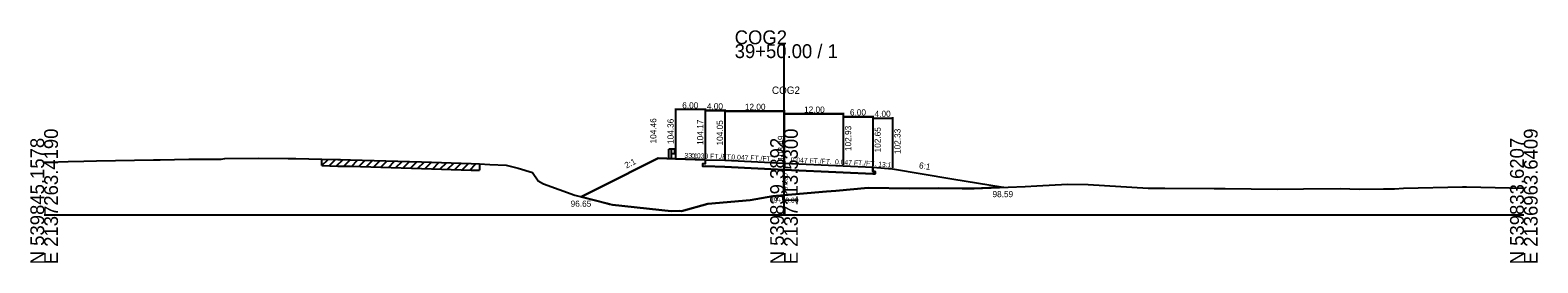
# Model space of a CAD drawing. Extents: x -13397 to 2303, y -10 to 39059.
# Drawn here: x 997.2 to 1302.8, y 18990.3 to 19037.4 of the extents above; entities that cross this region are included whole.
import ezdxf

# ---------------------------------------------------------------- set-up
doc = ezdxf.new("R2010")
doc.units = 0
for name, color, linetype in [('Level 1', 7, 'Continuous'), ('Level 5', 7, 'Continuous'), ('Level 53', 7, 'Continuous'), ('Level 54', 7, 'Continuous'), ('Level 55', 7, 'Continuous'), ('Level 7', 7, 'Continuous'), ('RD_GPK_XS_Cell', 7, 'Continuous'), ('RD_XS_EwShp', 7, 'Continuous'), ('RD_XS_ExGround', 7, 'Continuous'), ('RD_XS_ExPaveRet', 7, 'Continuous'), ('RD_XS_Pave', 7, 'Continuous'), ('RD_XS_TX_Baseline', 7, 'Continuous'), ('RD_XS_TX_Elev_EX', 7, 'Continuous'), ('RD_XS_TX_Elev_PR', 7, 'Continuous'), ('RD_XS_TX_Station', 7, 'Continuous')]:
    doc.layers.add(name, color=color, linetype=linetype)

msp = doc.modelspace()

# ---------------------------------------------------------------- linework, layer by layer
at = {"layer": 'Level 1'}
for p, q in [((1126.66, 19011.36), (1126.66, 19013.34)), ((1127.22, 19013.34), (1126.66, 19013.34)), ((1127.22, 19011.36), (1127.22, 19013.34)), ((1127.77, 19013.34), (1127.22, 19013.34)), ((1127.77, 19012.37), (1127.22, 19012.37)), ((1127.77, 19013.34), (1127.77, 19012.37)), ((1127.85, 19013.27), (1127.77, 19013.28)), ((1127.85, 19012.44), (1127.77, 19012.43)), ((1127.84, 19012.93), (1127.84, 19012.78)), ((1127.98, 19013.17), (1127.86, 19013.26)), ((1127.98, 19013.07), (1127.86, 19012.98)), ((1127.98, 19012.64), (1127.86, 19012.73)), ((1127.98, 19012.54), (1127.86, 19012.45))]:
    msp.add_line(p, q, dxfattribs=at)
for centre, radius, start, end in [((1127.91, 19012.93), 0.0651, 135, 180), ((1127.91, 19012.78), 0.0651, 180, 237.0105), ((1127.85, 19013.24), 0.026, 50.9495, 90), ((1127.85, 19012.47), 0.026, 270, 309.0504), ((1127.93, 19013.12), 0.0651, 309.0337, 50.9664), ((1127.93, 19012.59), 0.0651, 309.0337, 50.9664)]:
    msp.add_arc(centre, radius, start, end, dxfattribs=at)
at = {"layer": 'Level 5'}
for p, q in [((1133.5, 19010.36), (1133.5, 19009.86)), ((1134, 19010.34), (1133.5, 19010.36)), ((1134, 19011.17), (1134, 19010.34)), ((1133.5, 19009.86), (1134, 19009.84)), ((1138, 19009.72), (1134, 19009.84)), ((1138, 19009.72), (1134, 19009.84)), ((1138, 19009.72), (1134, 19009.84)), ((1134, 19009.84), (1138, 19009.72)), ((1150, 19009.16), (1138, 19009.72)), ((1150, 19009.16), (1138, 19009.72)), ((1150, 19009.16), (1138, 19009.72)), ((1138, 19009.72), (1150, 19009.16)), ((1138, 19009.72), (1150, 19009.16)), ((1162, 19008.59), (1150, 19009.16)), ((1162, 19008.59), (1150, 19009.16)), ((1150, 19009.16), (1162, 19008.59)), ((1150, 19009.16), (1162, 19008.59)), ((1150, 19009.16), (1162, 19008.59)), ((1168, 19008.31), (1162, 19008.59)), ((1162, 19008.59), (1168, 19008.31)), ((1162, 19008.59), (1168, 19008.31)), ((1162, 19008.59), (1168, 19008.31)), ((1168, 19009.65), (1168, 19008.81)), ((1168, 19008.81), (1168.5, 19008.79)), ((1168.5, 19008.29), (1168, 19008.31)), ((1168.5, 19008.79), (1168.5, 19008.29))]:
    msp.add_line(p, q, dxfattribs=at)
at = {"layer": 'Level 54'}
for p, q in [((1128, 19021.51), (1128, 19011.56)), ((1134, 19021.31), (1128, 19021.31)), ((1134, 19021.51), (1134, 19011.37)), ((1134, 19021.32), (1134, 19011.37)), ((1134, 19021.32), (1134, 19011.37)), ((1134, 19021.32), (1134, 19011.37)), ((1134, 19021.32), (1134, 19011.37)), ((1134, 19021.12), (1138, 19021.12)), ((1134, 19021.12), (1138, 19021.12)), ((1134, 19021.12), (1138, 19021.12)), ((1138, 19021.12), (1134, 19021.12)), ((1138, 19021.32), (1138, 19011.25)), ((1138, 19021.32), (1138, 19011.25)), ((1138, 19021.32), (1138, 19011.25)), ((1138, 19021.32), (1138, 19011.25)), ((1138, 19021.2), (1138, 19011.25)), ((1138, 19021.2), (1138, 19011.25)), ((1138, 19021.2), (1138, 19011.25)), ((1138, 19021.2), (1138, 19011.25)), ((1138, 19021.2), (1138, 19011.25)), ((1138, 19021), (1150, 19021)), ((1138, 19021), (1150, 19021)), ((1138, 19021), (1150, 19021)), ((1150, 19021), (1138, 19021)), ((1150, 19021), (1138, 19021)), ((1150, 19021.2), (1150, 19010.69)), ((1150, 19021.2), (1150, 19010.69)), ((1150, 19021.2), (1150, 19010.69)), ((1150, 19021.2), (1150, 19010.69)), ((1150, 19021.2), (1150, 19010.69)), ((1150, 19020.64), (1150, 19010.69)), ((1150, 19020.64), (1150, 19010.69)), ((1150, 19020.64), (1150, 19010.69)), ((1150, 19020.64), (1150, 19010.69)), ((1150, 19020.64), (1150, 19010.69)), ((1150, 19020.44), (1162, 19020.44)), ((1150, 19020.44), (1162, 19020.44)), ((1162, 19020.44), (1150, 19020.44)), ((1162, 19020.44), (1150, 19020.44)), ((1162, 19020.44), (1150, 19020.44)), ((1162, 19020.64), (1162, 19010.13)), ((1162, 19020.64), (1162, 19010.13)), ((1162, 19020.64), (1162, 19010.13)), ((1162, 19020.64), (1162, 19010.13)), ((1162, 19020.64), (1162, 19010.13)), ((1162, 19020.08), (1162, 19010.13)), ((1162, 19020.08), (1162, 19010.13)), ((1162, 19020.08), (1162, 19010.13)), ((1162, 19020.08), (1162, 19010.13)), ((1162, 19019.88), (1168, 19019.88)), ((1168, 19019.88), (1162, 19019.88)), ((1168, 19019.88), (1162, 19019.88)), ((1168, 19019.88), (1162, 19019.88)), ((1168, 19020.08), (1168, 19009.85)), ((1168, 19020.08), (1168, 19009.85)), ((1168, 19020.08), (1168, 19009.85)), ((1168, 19020.08), (1168, 19009.85)), ((1168, 19019.8), (1168, 19009.85)), ((1168, 19019.6), (1172, 19019.6)), ((1172, 19019.8), (1172, 19009.53))]:
    msp.add_line(p, q, dxfattribs=at)
at = {"layer": 'Level 7'}
for p, q in [((1124.5, 19011.46), (1112.5, 19005.46)), ((1128, 19011.36), (1124.5, 19011.46)), ((1134, 19011.17), (1128, 19011.36)), ((1168, 19009.65), (1172, 19009.33)), ((1172, 19009.33), (1184, 19007.33)), ((1184, 19007.33), (1194.42, 19005.59)), ((1112.5, 19005.46), (1108.87, 19003.65))]:
    msp.add_line(p, q, dxfattribs=at)
at = {"layer": 'RD_GPK_XS_Cell'}
for p, q in [((1150, 19000), (1150, 19034.55)), ((1000, 19000), (1150, 19000)), ((1150, 19000), (1300, 19000))]:
    msp.add_line(p, q, dxfattribs=at)
at = {"layer": 'RD_XS_EwShp'}
msp.add_lwpolyline([(1134, 19011.17), (1134, 19010.34), (1133.5, 19010.36), (1133.5, 19009.86), (1134, 19009.84), (1138, 19009.72), (1150, 19009.16), (1162, 19008.59), (1168, 19008.31), (1168.5, 19008.29), (1168.5, 19008.79), (1168, 19008.81), (1168, 19009.65), (1172, 19009.33), (1184, 19007.33), (1194.42, 19005.59), (1188.54, 19005.38), (1186.09, 19005.34), (1181.31, 19005.43), (1175.54, 19005.35), (1167.06, 19005.47), (1160.52, 19004.86), (1158.63, 19004.76), (1150, 19004), (1147.74, 19003.8), (1143.13, 19003), (1134.58, 19002.23), (1129.24, 19000.76), (1128.85, 19000.85), (1127.1, 19000.79), (1115.25, 19002.05), (1114.65, 19002.17), (1114.15, 19002.31), (1108.87, 19003.65), (1112.5, 19005.46), (1124.5, 19011.46), (1128, 19011.36)], close=True, dxfattribs=at)
at = {"layer": 'RD_XS_ExGround'}
for p, q in [((1000, 19010.65), (1000.87, 19010.69)), ((1000.87, 19010.69), (1004.87, 19010.8)), ((1004.87, 19010.8), (1008.05, 19010.89)), ((1008.05, 19010.89), (1010.6, 19010.94)), ((1010.6, 19010.94), (1022.19, 19011.16)), ((1022.19, 19011.16), (1023.55, 19011.18)), ((1023.55, 19011.18), (1029.32, 19011.3)), ((1029.32, 19011.3), (1033.56, 19011.29)), ((1033.56, 19011.29), (1034.77, 19011.27)), ((1034.77, 19011.27), (1035.38, 19011.27)), ((1035.38, 19011.27), (1035.9, 19011.29)), ((1035.9, 19011.29), (1036.6, 19011.45)), ((1036.6, 19011.45), (1043.5, 19011.52)), ((1043.5, 19011.52), (1049.44, 19011.42)), ((1049.44, 19011.42), (1051.03, 19011.39)), ((1051.03, 19011.39), (1056.28, 19011.28)), ((1056.28, 19011.28), (1059.52, 19011.2)), ((1059.52, 19011.2), (1060.08, 19011.19)), ((1060.08, 19011.19), (1062.11, 19011.14)), ((1062.11, 19011.14), (1076.52, 19010.73)), ((1076.52, 19010.73), (1086.54, 19010.38)), ((1086.54, 19010.38), (1088.27, 19010.33)), ((1088.27, 19010.33), (1090.37, 19010.23)), ((1090.37, 19010.23), (1093.64, 19010.07)), ((1093.64, 19010.07), (1096.12, 19009.44)), ((1096.12, 19009.44), (1098.99, 19008.59)), ((1098.99, 19008.59), (1100.13, 19006.89)), ((1100.13, 19006.89), (1101.21, 19006.29)), ((1101.21, 19006.29), (1107.6, 19003.97)), ((1150, 19004), (1158.63, 19004.76)), ((1158.63, 19004.76), (1160.52, 19004.86)), ((1160.52, 19004.86), (1167.06, 19005.47)), ((1167.06, 19005.47), (1175.54, 19005.35)), ((1175.54, 19005.35), (1181.31, 19005.43)), ((1181.31, 19005.43), (1186.09, 19005.34)), ((1186.09, 19005.34), (1188.54, 19005.38)), ((1188.54, 19005.38), (1198.87, 19005.75)), ((1198.87, 19005.75), (1201.26, 19005.92)), ((1201.26, 19005.92), (1207.51, 19006.24)), ((1207.51, 19006.24), (1211.66, 19006.17)), ((1211.66, 19006.17), (1223.8, 19005.42)), ((1223.8, 19005.42), (1224.44, 19005.41)), ((1224.44, 19005.41), (1227.22, 19005.41)), ((1227.22, 19005.41), (1237.22, 19005.36)), ((1237.22, 19005.36), (1239.42, 19005.33)), ((1239.42, 19005.33), (1250.01, 19005.22)), ((1250.01, 19005.22), (1255.34, 19005.31)), ((1255.34, 19005.31), (1262.79, 19005.35)), ((1262.79, 19005.35), (1266.67, 19005.24)), ((1266.67, 19005.24), (1271.57, 19005.29)), ((1271.57, 19005.29), (1273.76, 19005.3)), ((1273.76, 19005.3), (1275.57, 19005.4)), ((1275.57, 19005.4), (1287.56, 19005.71)), ((1287.56, 19005.71), (1288.36, 19005.69)), ((1288.36, 19005.69), (1300, 19005.44)), ((1107.6, 19003.97), (1114.15, 19002.31)), ((1114.15, 19002.31), (1114.65, 19002.17)), ((1114.65, 19002.17), (1115.25, 19002.05)), ((1115.25, 19002.05), (1127.1, 19000.79)), ((1129.24, 19000.76), (1134.58, 19002.23)), ((1134.58, 19002.23), (1143.13, 19003)), ((1143.13, 19003), (1147.74, 19003.8)), ((1147.74, 19003.8), (1150, 19004)), ((1127.1, 19000.79), (1128.85, 19000.85)), ((1128.85, 19000.85), (1129.24, 19000.76))]:
    msp.add_line(p, q, dxfattribs=at)
at = {"layer": 'RD_XS_ExPaveRet'}
for p, q in [((1056.28, 19009.98), (1056.28, 19011.28)), ((1056.28, 19009.98), (1057.55, 19011.25)), ((1057.78, 19009.94), (1059.05, 19011.21)), ((1059.28, 19009.91), (1060.55, 19011.18)), ((1060.78, 19009.87), (1062.05, 19011.14)), ((1062.28, 19009.83), (1063.55, 19011.1)), ((1063.78, 19009.79), (1065.05, 19011.05)), ((1065.28, 19009.75), (1066.55, 19011.01)), ((1066.78, 19009.7), (1068.05, 19010.97)), ((1068.28, 19009.66), (1069.55, 19010.93)), ((1069.78, 19009.62), (1071.05, 19010.88)), ((1071.28, 19009.58), (1072.55, 19010.84)), ((1072.78, 19009.53), (1074.05, 19010.8)), ((1074.28, 19009.49), (1075.55, 19010.76)), ((1075.78, 19009.45), (1077.04, 19010.71)), ((1077.28, 19009.4), (1078.54, 19010.66)), ((1078.78, 19009.35), (1080.04, 19010.61)), ((1080.28, 19009.3), (1081.54, 19010.55)), ((1081.78, 19009.25), (1083.04, 19010.5)), ((1083.28, 19009.19), (1084.54, 19010.45)), ((1084.78, 19009.14), (1086.04, 19010.4)), ((1086.28, 19009.09), (1087.54, 19010.35)), ((1056.28, 19009.98), (1059.52, 19009.9)), ((1059.52, 19009.9), (1060.08, 19009.89)), ((1060.08, 19009.89), (1062.11, 19009.84)), ((1062.11, 19009.84), (1076.52, 19009.43)), ((1076.52, 19009.43), (1086.54, 19009.08)), ((1086.54, 19009.08), (1088.27, 19009.03)), ((1088.27, 19010.33), (1088.27, 19009.03))]:
    msp.add_line(p, q, dxfattribs=at)
at = {"layer": 'RD_XS_Pave'}
for p, q in [((1134, 19011.17), (1138, 19011.05)), ((1138, 19011.05), (1150, 19010.49)), ((1150, 19010.49), (1162, 19009.93)), ((1162, 19009.93), (1168, 19009.65))]:
    msp.add_line(p, q, dxfattribs=at)

# ---------------------------------------------------------------- texts
at = {"layer": 'Level 53'}
for s, rotation, p in [('104.46', 90, (1124.12, 19014.46)), ('104.36', 90, (1127.62, 19014.36)), ('104.17', 90, (1133.62, 19014.17)), ('104.05', 90, (1137.62, 19014.05)), ('104.05', 90, (1137.62, 19014.05)), ('104.05', 90, (1137.62, 19014.05)), ('102.93', 90, (1163.62, 19012.93)), ('102.93', 90, (1163.62, 19012.93)), ('102.93', 90, (1163.62, 19012.93)), ('102.65', 90, (1169.62, 19012.65)), ('102.33', 90, (1173.62, 19012.33)), ('2:1', 26.5651, (1118.05, 19009.36)), ('6:1', 350.5377, (1177.3, 19009.46))]:
    msp.add_text(s, height=1.25, rotation=rotation, dxfattribs=at).set_placement(p)
for s, p in [('98.59', (1192.27, 19003.59)), ('96.65', (1106.74, 19001.65))]:
    msp.add_text(s, height=1.25, dxfattribs=at).set_placement(p)
at = {"layer": 'Level 54'}
for s, p in [('6.00', (1129.37, 19021.56)), ('4.00', (1134.37, 19021.37)), ('4.00', (1134.37, 19021.37)), ('4.00', (1134.37, 19021.37)), ('4.00', (1134.37, 19021.37)), ('12.00', (1142.07, 19021.25)), ('12.00', (1142.07, 19021.25)), ('12.00', (1142.07, 19021.25)), ('12.00', (1142.07, 19021.25)), ('12.00', (1142.07, 19021.25)), ('12.00', (1154.07, 19020.69)), ('12.00', (1154.07, 19020.69)), ('12.00', (1154.07, 19020.69)), ('12.00', (1154.07, 19020.69)), ('12.00', (1154.07, 19020.69)), ('6.00', (1163.37, 19020.13)), ('6.00', (1163.37, 19020.13)), ('6.00', (1163.37, 19020.13)), ('6.00', (1163.37, 19020.13)), ('4.00', (1168.37, 19019.85))]:
    msp.add_text(s, height=1.25, dxfattribs=at).set_placement(p)
at = {"layer": 'Level 55'}
for s, rotation, p in [('33:1', 358.2638, (1129.79, 19011.55)), ('0.030 FT./FT.', 358.2638, (1131.18, 19011.51)), ('0.030 FT./FT.', 358.2638, (1131.18, 19011.51)), ('0.030 FT./FT.', 358.2638, (1131.18, 19011.51)), ('0.030 FT./FT.', 358.2638, (1131.18, 19011.51)), ('0.047 FT./FT.', 357.3162, (1139.32, 19011.24)), ('0.047 FT./FT.', 357.3162, (1139.32, 19011.24)), ('0.047 FT./FT.', 357.3162, (1139.32, 19011.24)), ('0.047 FT./FT.', 357.3162, (1139.32, 19011.24)), ('0.047 FT./FT.', 357.3162, (1139.32, 19011.24)), ('0.047 FT./FT.', 357.3162, (1151.32, 19010.68)), ('0.047 FT./FT.', 357.3162, (1151.32, 19010.68)), ('0.047 FT./FT.', 357.3162, (1151.32, 19010.68)), ('0.047 FT./FT.', 357.3162, (1151.32, 19010.68)), ('0.047 FT./FT.', 357.3162, (1151.32, 19010.68)), ('0.047 FT./FT.', 357.3162, (1160.32, 19010.26)), ('0.047 FT./FT.', 357.3162, (1160.32, 19010.26)), ('0.047 FT./FT.', 357.3162, (1160.32, 19010.26)), ('0.047 FT./FT.', 357.3162, (1160.32, 19010.26)), ('13:1', 355.4261, (1169.07, 19009.81))]:
    msp.add_text(s, height=1, rotation=rotation, dxfattribs=at).set_placement(p)
at = {"layer": 'RD_GPK_XS_Cell'}
for s, p in [('COG2', (1140, 19034.55)), ('39+50.00 / 1', (1140, 19031.75))]:
    msp.add_text(s, height=2.8, dxfattribs=at).set_placement(p)
for s, p in [('E 2137263.4190', (1002.8, 18990)), ('E 2137113.5300', (1152.8, 18990)), ('E 2136963.6409', (1302.8, 18990)), ('N 539845.1578', (1000, 18990)), ('N 539839.3892', (1150, 18990)), ('N 539833.6207', (1300, 18990))]:
    msp.add_text(s, height=2.8, rotation=90, dxfattribs=at).set_placement(p)
at = {"layer": 'RD_XS_TX_Baseline'}
msp.add_text('COG2', height=1.5, dxfattribs=at).set_placement((1147.55, 19024.49))
at = {"layer": 'RD_XS_TX_Elev_EX'}
msp.add_text('97.00', height=1, rotation=90, dxfattribs=at).set_placement((1150.75, 19005))
at = {"layer": 'RD_XS_TX_Elev_PR'}
msp.add_text(' 103.49', height=1.25, rotation=90, dxfattribs=at).set_placement((1150, 19010.49))
at = {"layer": 'RD_XS_TX_Station'}
msp.add_text('39+50.00', height=1, dxfattribs=at).set_placement((1147.15, 19002.49))

doc.saveas('drawing.dxf')
